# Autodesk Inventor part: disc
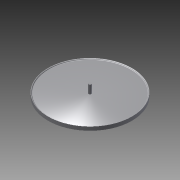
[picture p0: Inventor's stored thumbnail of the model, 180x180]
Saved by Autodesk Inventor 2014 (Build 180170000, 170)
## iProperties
Created: 2013-08
Part Number: disc
Material: Типовые
Document SubType Name: Modeling
Designer: ed
Density: 1 g/cm^3
Appearance: По умолчанию
Author: ed
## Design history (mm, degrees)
sketch "Эскиз1"
  geometry: C1 r 150 at (0, 0); C2 r 5 at (0, 0); 1 further point
  constraints: 2 centre point, 2 coincident
  dimensions: "d0" = 300 diameter of C1; "d1" = 10 diameter of C2
extrude "Выдавливание1" new body sketch "Эскиз1" distance "d2" = 10; taper "d3" = 0 deg
sketch "Эскиз2"
  geometry: C1 r 5 at (0, 0) reference
extrude "Выдавливание2" join sketch "Эскиз2" distance "d4" = 10; taper "d5" = 0 deg; dims "d11" = 30, "d12" = 0
sketch "Эскиз3"
  geometry: C1 r 150 at (0, 0) reference; C2 r 150 at (0, 0); C3 r 147.5 at (0, 0)
  constraints: 2 centre point, 2 coincident, 1 concentric
  dimensions: "d6" = 295 diameter of C3
extrude "Выдавливание3" join sketch "Эскиз3" distance "d7" = 3; taper "d8" = 0 deg
fillet "Сопряжение1" dims "d9" = 2
fillet "Сопряжение2" dims "d10" = 2
node "Твердое тело1"
